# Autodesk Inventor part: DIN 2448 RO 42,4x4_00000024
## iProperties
Created: 2006-02
Part Number: DIN 2448 RO 42,4x4_00000024
Material: Default
Document SubType Name: Modeling
Designer: FranzK
Stock Number: DIN 2448 RO 42,4x4
Mass: 439.97 g
Surface Area: 2207.83 cm^2
Volume: 439.97 cm^3
Density: 1 g/cm^3
G_L: 894.000 mm
G_W: 42.400 mm
G_H: 42.400 mm
AFG_Item: 42.4 x 4
CSToolsMass: 0.4
CSToolsVolume: 439970.0
CSToolsArea: 2208.0
Author: FranzK
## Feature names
1. AFG_Detailed_DIN 2448 RO 42,4x4_00000024 [Extrusion]
2. AFG_Simplified_DIN 2448 RO 42,4x4_00000024 [Extrusion]
3. Extrusion5
